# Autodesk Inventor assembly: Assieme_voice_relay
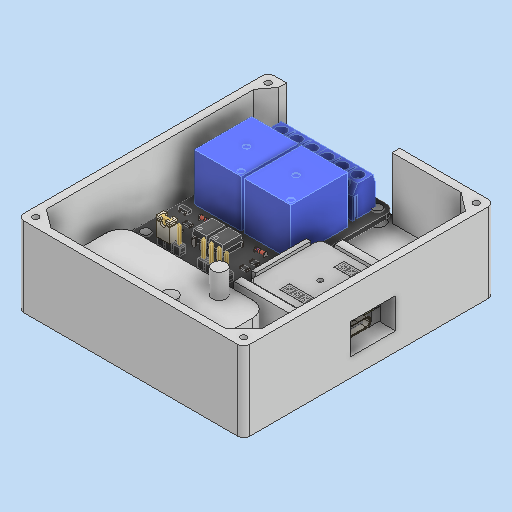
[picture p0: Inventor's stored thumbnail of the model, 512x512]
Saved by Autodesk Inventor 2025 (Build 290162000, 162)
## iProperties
Created: 2025-03
Part Number: Assieme_voice_relay
Document SubType Name: Assembly
Designer: Ryzen5700u
Author: Ryzen5700u
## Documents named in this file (6)
- C:\Users\Ryzen5700u\Desktop\voice relay\Assieme_voice_relay.iam
- C:\Users\Ryzen5700u\Desktop\voice relay\M5stack_ASR_unit.ipt
- C:\Users\Ryzen5700u\Desktop\voice relay\RelayBoard\RelayBoard.ipt
- C:\Users\Ryzen5700u\Desktop\voice relay\protesi_mano_servo\M5 ATOM Lite.ipt
- C:\Users\Ryzen5700u\Desktop\voice relay\scatola_voice.ipt
- C:\Users\Ryzen5700u\Desktop\voice relay\tappo.ipt
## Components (5 placed, 5 different names)
1. M5stack_ASR_unit:1 — Coincidente:1, Coincidente:2, Allineato:3, Allineato:4, Allineato:6
2. RelayBoard:1 — Coincidente:1, Coincidente:3
3. M5 ATOM Lite:2 — Coincidente:2, Allineato:3, Coincidente:3, Allineato:5
4. scatola_voice:1 — Allineato:4, Allineato:5, Allineato:6, Allineato:7
5. tappo:1 — Allineato:7
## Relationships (8: Flush 5, Mate 3)
- Coincidente:1 [Mate]: M5stack_ASR_unit:1 ↔ RelayBoard:1
- Coincidente:2 [Mate]: M5stack_ASR_unit:1 ↔ M5 ATOM Lite:2
- Allineato:3 [Flush]: M5stack_ASR_unit:1 ↔ M5 ATOM Lite:2
- Coincidente:3 [Mate]: RelayBoard:1 ↔ M5 ATOM Lite:2
- Allineato:4 [Flush]: M5stack_ASR_unit:1 ↔ scatola_voice:1
- Allineato:5 [Flush]: M5 ATOM Lite:2 ↔ scatola_voice:1
- Allineato:6 [Flush]: M5stack_ASR_unit:1 ↔ scatola_voice:1
- Allineato:7 [Flush]: scatola_voice:1 ↔ tappo:1
